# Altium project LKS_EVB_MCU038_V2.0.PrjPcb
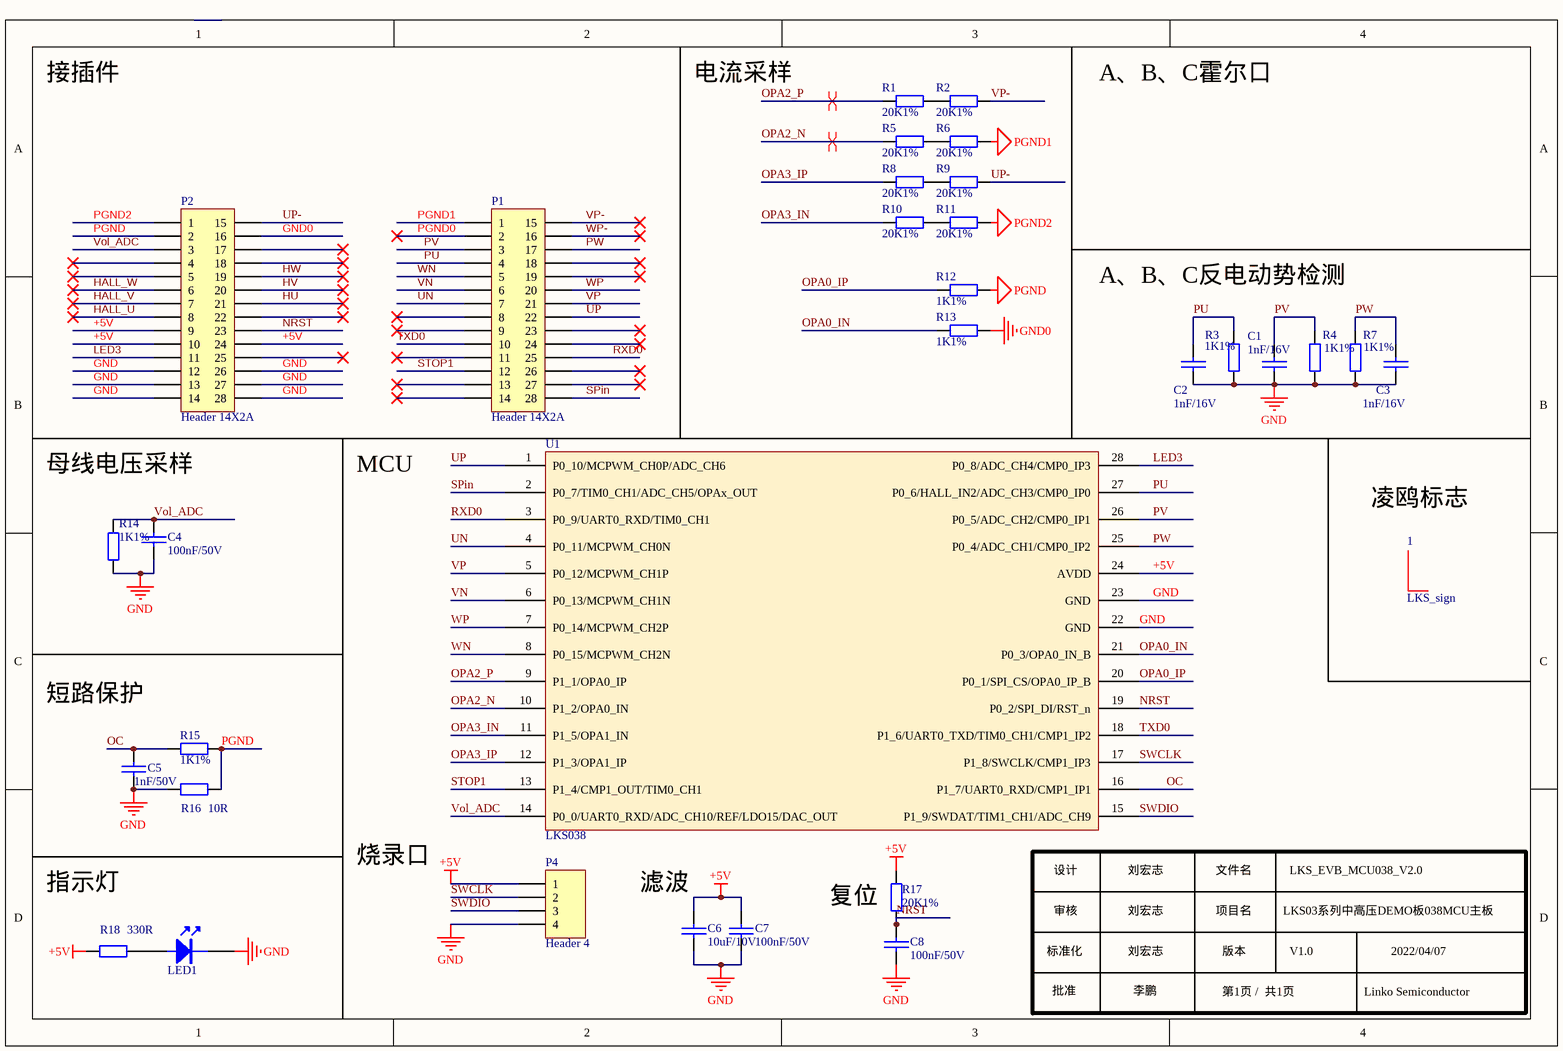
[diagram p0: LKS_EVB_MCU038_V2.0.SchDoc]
1 sheet, 32 parts. Net scope: global (net labels, ports and power ports of the same name join across sheets).
Board file: LKS_EVB_MCU038_V2.0.PcbDoc

## Sheet LKS_EVB_MCU038_V2.0.SchDoc
size A4; SheetNumber: 1; SheetTotal: 1

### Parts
1  LKS_sign  [LKS_LOGO2]
C1  1nF/16V  [0603C]
C2  1nF/16V  [0603C]
C3  1nF/16V  [0603C]
C4  100nF/50V  [0603C]
C5  1nF/50V  [0603C]
C6  10uF/10V  [0603C]
C7  100nF/50V  [0603C]
C8  100nF/50V  [0603C]
LED1  LED  [0603D]  (value not drawn)
P1  Header 14X2A  [HDR2X14_CEN]
P2  Header 14X2A  [HDR2X14_CEN]
P4  Header 4  [HDR1X4]
R1  20K1%  [0603R]
R2  20K1%  [0603R]
R3  1K1%  [0603R]
R4  1K1%  [0603R]
R5  20K1%  [0603R]
R6  20K1%  [0603R]
R7  1K1%  [0603R]
R8  20K1%  [0603R]
R9  20K1%  [0603R]
R10  20K1%  [0603R]
R11  20K1%  [0603R]
R12  1K1%  [0603R]
R13  1K1%  [0603R]
R14  1K1%  [0603R]
R15  1K1%  [0603R]
R16  10R  [0603R]
R17  20K1%  [0603R]
R18  330R  [0603R]
U1  LKS038  [TSSOP-28]

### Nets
+5V: C6.2 C7.2 P2.9 P2.10 P2.24 P4.1 R17.2 R18.1 U1.24(AVDD)
GND: C1.2 C2.2 C3.2 C4.1 C5.1 C6.1 C7.1 C8.2 LED1.2(K) P2.12 P2.13 P2.14 P2.26 P2.27 P2.28 P4.4 R3.2 R4.2 R7.2 R14.1 R16.2 U1.22(GND) U1.23(GND)
GND0: P2.16 R13.1
PGND: P2.2 R12.1 R15.2 R16.1
PGND1: P1.1 R6.1
PGND2: P2.1 R11.1
HALL_U: P2.8
HALL_V: P2.7
HALL_W: P2.6
HU: P2.21
HV: P2.20
HW: P2.19
LED3: P2.11 U1.28(P0_8/ADC_CH4/CMP0_IP3)
NRST: C8.1 P2.23 R17.1 U1.19(P0_2/SPI_DI/RST_n)
OC: C5.2 R15.1 U1.16(P1_7/UART0_RXD/CMP1_IP1)
OPA0_IN: R13.2 U1.21(P0_3/OPA0_IN_B)
OPA0_IP: R12.2 U1.20(P0_1/SPI_CS/OPA0_IP_B)
OPA2_N: R5.2 U1.10(P1_2/OPA0_IN)
OPA2_P: R1.2 U1.9(P1_1/OPA0_IP)
OPA3_IN: R10.2 U1.11(P1_5/OPA1_IN)
OPA3_IP: R8.2 U1.12(P1_3/OPA1_IP)
PGND0: P1.2
PU: C2.1 P1.4 R3.1 U1.27(P0_6/HALL_IN2/ADC_CH3/CMP0_IP0)
PV: C1.1 P1.3 R4.1 U1.26(P0_5/ADC_CH2/CMP0_IP1)
PW: C3.1 P1.17 R7.1 U1.25(P0_4/ADC_CH1/CMP0_IP2)
RXD0: P1.25 U1.3(P0_9/UART0_RXD/TIM0_CH1)
SPin: P1.28 U1.2(P0_7/TIM0_CH1/ADC_CH5/OPAx_OUT)
STOP1: P1.12 U1.13(P1_4/CMP1_OUT/TIM0_CH1)
SWCLK: P4.2 U1.17(P1_8/SWCLK/CMP1_IP3)
SWDIO: P4.3 U1.15(P1_9/SWDAT/TIM1_CH1/ADC_CH9)
TXD0: P1.10 U1.18(P1_6/UART0_TXD/TIM0_CH1/CMP1_IP2)
UN: P1.7 U1.4(P0_11/MCPWM_CH0N)
UP: P1.22 U1.1(P0_10/MCPWM_CH0P/ADC_CH6)
UP-: P2.15 R9.1
VN: P1.6 U1.6(P0_13/MCPWM_CH1N)
Vol_ADC: C4.2 P2.3 R14.2 U1.14(P0_0/UART0_RXD/ADC_CH10/REF/LDO15/DAC_OUT)
VP: P1.21 U1.5(P0_12/MCPWM_CH1P)
VP-: P1.15 R2.1
WN: P1.5 U1.8(P0_15/MCPWM_CH2N)
WP: P1.20 U1.7(P0_14/MCPWM_CH2P)
WP-: P1.16
NetLED1_1: LED1.1(A) R18.2
NetR1_1: R1.1 R2.2
NetR5_1: R5.1 R6.2
NetR8_1: R8.1 R9.2
NetR10_1: R10.1 R11.2

Not connected (* = marked no-connect by the designer): P1 8* 9* 11* 13* 14* 18* 19* 23* 24* 26* 27*; P2 4* 5* 17* 18* 22* 25*

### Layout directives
differential pair: OPA2_N, OPA2_P

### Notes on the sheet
- 接插件
- 电流采样
- A、B、C霍尔口
- A、B、C反电动势检测
- 母线电压采样
- MCU
- (near 1) 凌鸥标志
- 短路保护
- 烧录口
- 指示灯
- 滤波
- 复位
- (near U1) 设计
- 审核
- 刘宏志
- 文件名
- 项目名
- LKS03系列中高压DEMO板038MCU主板
- LKS_EVB_MCU038_V2.0
- 标准化
- 批准
- 李鹏
- 版本
- 第1页 /  共1页
- V1.0
- Linko Semiconductor
- 2022/04/07

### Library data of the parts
C1-C3 = CAP: Capacitor
C4-C8 = C: Capacitor
LED1 = LED: LED_Light
P1 P2 = Header 14X2A: Header, 14-Pin, Dual row
P4 = Header 4: Header, 4-Pin
R1-R17 = Res: Resistor; Value: K
R18 = Res: Resistor; Value: 330
U1 = LKS32MC038Y6P8: CHIP--TSSOP28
